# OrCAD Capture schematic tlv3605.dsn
size A
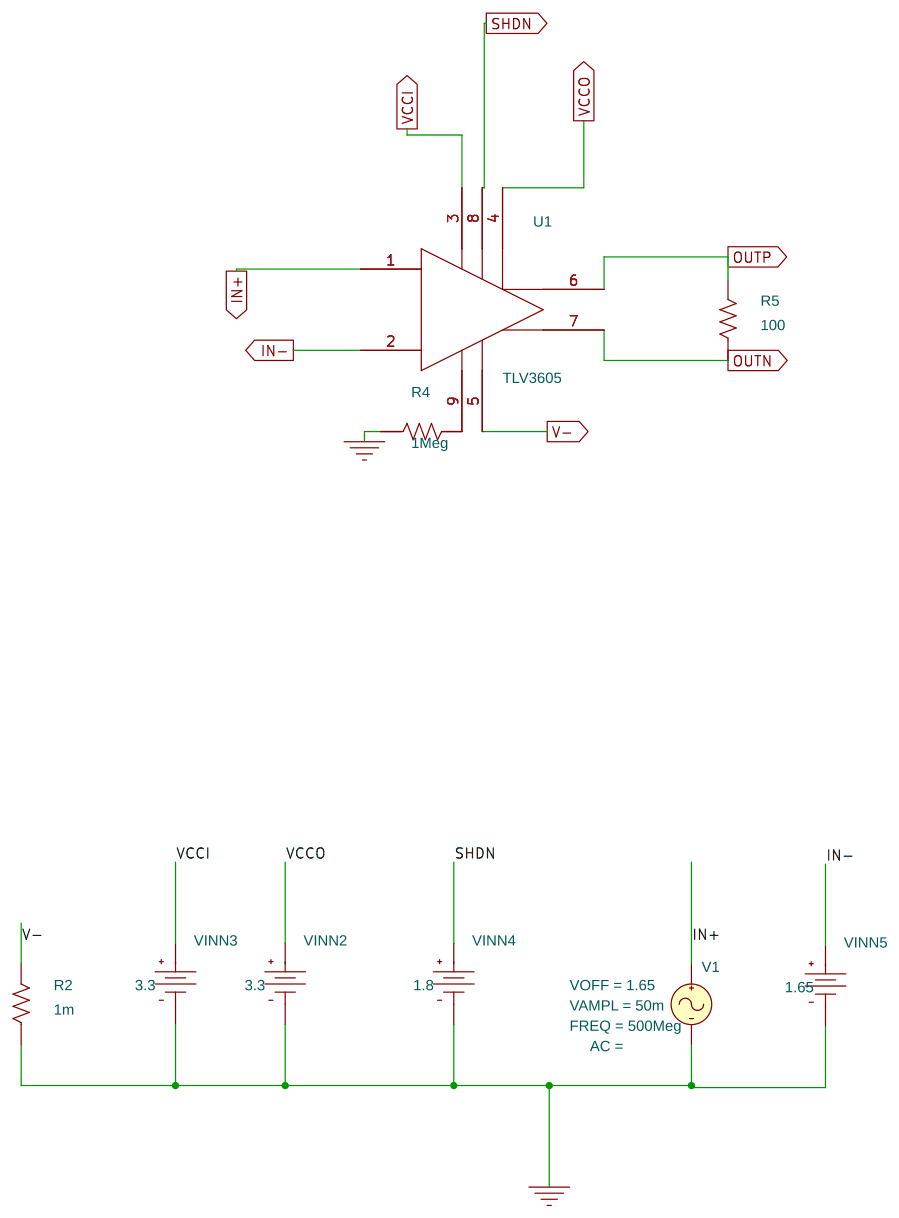
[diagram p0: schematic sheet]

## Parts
R2  1m  [AXRC05]
R4  1Meg  [AXRC05]
R5  100  [AXRC05]
U1  TLV3605
V1  VSIN
VINN2  VDC
VINN3  VDC
VINN4  VDC
VINN5  VDC

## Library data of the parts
R2 R4 R5 = R
U1 = TLV3605
V1 = VSIN: FREQ: 500Meg; VAMPL: 50m; VOFF: 1.65
VINN2 VINN3 = VDC: DC: 3.3
VINN4 = VDC: DC: 1.8
VINN5 = VDC: DC: 1.65

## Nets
VCCI: U1.3(VCCI) VINN3.0(+)
VCCO: U1.4(VCCO) VINN2.0(+)
0: R2.1 R4.1 V1.2(-) VINN2.1(-) VINN3.1(-) VINN4.1(-) VINN5.1(-)
IN+: U1.1(IN+) V1.1(+)
IN-: U1.2(IN-) VINN5.0(+)
OUTN: R5.1 U1.7(OUTN)
OUTP: R5.2 U1.6(OUTP)
SHDN: U1.8(SHDN) VINN4.0(+)
V-: R2.2 U1.5(VEE)
N849159: R4.2 U1.9(LE_HYST)
